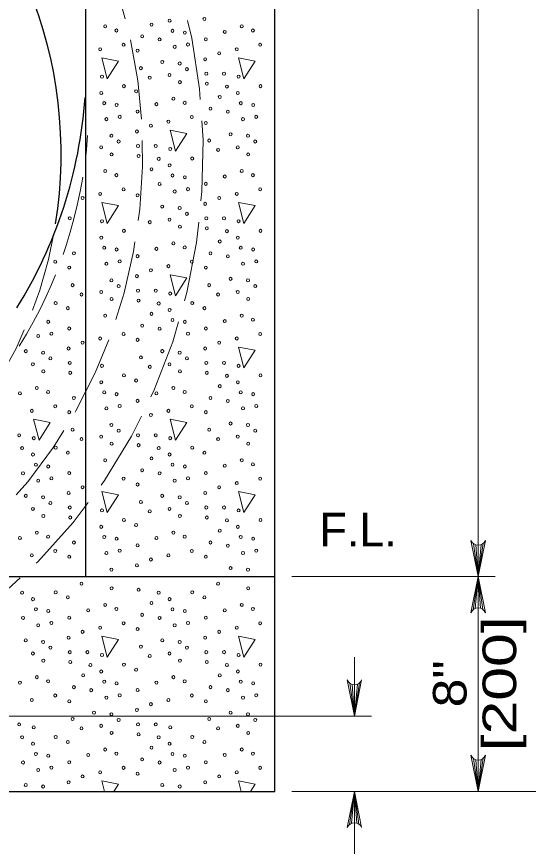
# Model space of a CAD drawing. Extents: x 1083.1 to 1117.1, y 697.4 to 719.4.
# Drawn here: x 1090.667 to 1093.045, y 700.066 to 703.92 of the extents above; entities that cross this region are included whole.
import ezdxf
from ezdxf.enums import TextEntityAlignment as Align

# ---------------------------------------------------------------- set-up
doc = ezdxf.new("R2010")
doc.units = 0
doc.header["$LTSCALE"] = 0.062
doc.linetypes.add('LONG_DASHED', pattern=[7.5, 6, -1.5])
doc.layers.add('1', color=7, linetype='Continuous', lineweight=13)

msp = doc.modelspace()

# ---------------------------------------------------------------- linework, layer by layer
at = {"layer": '1'}
for p, q in [((1092.8115, 701.31858), (1092.8115, 707.72683)), ((1092.79017, 701.47092), (1092.8115, 701.31858)), ((1092.80075, 701.46575), (1092.8115, 701.31858)), ((1092.835, 701.47267), (1092.8115, 701.31858)), ((1092.82517, 701.46683), (1092.8115, 701.31858)), ((1092.8115, 701.46417), (1092.8115, 701.31858)), ((1092.89017, 701.31858), (1091.946, 701.31858)), ((1092.78792, 701.1645), (1092.8115, 701.31858)), ((1092.79783, 701.17033), (1092.8115, 701.31858)), ((1092.8115, 701.31858), (1092.8115, 700.32125)), ((1092.8115, 701.173), (1092.8115, 701.31858)), ((1092.82225, 701.17142), (1092.8115, 701.31858)), ((1092.83283, 701.16625), (1092.8115, 701.31858)), ((1092.23658, 700.67117), (1092.23658, 700.94517)), ((1092.21533, 700.8235), (1092.23658, 700.67117)), ((1092.22583, 700.81833), (1092.23658, 700.67117)), ((1092.26017, 700.82525), (1092.23658, 700.67117)), ((1092.25033, 700.81942), (1092.23658, 700.67117)), ((1092.23658, 700.81675), (1092.23658, 700.67117)), ((1092.31558, 700.67117), (1089.08633, 700.67117)), ((1092.79017, 700.4735), (1092.8115, 700.32125)), ((1092.80075, 700.46842), (1092.8115, 700.32125)), ((1092.835, 700.47533), (1092.8115, 700.32125)), ((1092.82517, 700.4695), (1092.8115, 700.32125)), ((1092.8115, 700.46683), (1092.8115, 700.32125)), ((1091.06317, 700.37008), (1091.07608, 700.32133)), ((1091.14108, 700.355), (1091.06317, 700.37008)), ((1091.11967, 700.32133), (1091.14108, 700.355)), ((1091.75408, 700.32133), (1091.7755, 700.355)), ((1093.83458, 700.32125), (1091.946, 700.32125)), ((1092.21308, 700.16717), (1092.23658, 700.32125)), ((1092.22292, 700.173), (1092.23658, 700.32125)), ((1092.23658, 700.17567), (1092.23658, 700.32125)), ((1092.24742, 700.17408), (1092.23658, 700.32125)), ((1092.25792, 700.16892), (1092.23658, 700.32125)), ((1092.23658, 699.00258), (1092.23658, 700.32125))]:
    msp.add_line(p, q, dxfattribs=at)
at = {"layer": '1', "lineweight": 25}
for p, q in [((1090.98767, 704.14825), (1090.98767, 701.31858)), ((1091.86725, 700.32092), (1091.86725, 704.12275)), ((1086.25067, 701.31858), (1091.86725, 701.31858))]:
    msp.add_line(p, q, dxfattribs=at)
msp.add_lwpolyline([(1086.25067, 706.14383), (1086.25067, 700.32125), (1091.86725, 700.32125)], dxfattribs=at)
at = {"layer": '1'}
for points in [[(1091.06317, 703.72833), (1091.08883, 703.631), (1091.14108, 703.71317)], [(1091.69767, 703.72833), (1091.72325, 703.631), (1091.7755, 703.71317)], [(1091.38042, 703.3925), (1091.40608, 703.29525), (1091.45825, 703.37742)], [(1091.06317, 703.05675), (1091.08883, 702.95942), (1091.14108, 703.04158)], [(1091.69767, 703.05675), (1091.72325, 702.95942), (1091.7755, 703.04158)], [(1091.38042, 702.72092), (1091.40608, 702.6235), (1091.45825, 702.70567)], [(1091.69767, 702.385), (1091.72325, 702.28775), (1091.7755, 702.36992)], [(1090.746, 702.04925), (1090.77167, 701.95192), (1090.82383, 702.03408)], [(1091.38042, 702.04925), (1091.40608, 701.95192), (1091.45825, 702.03408)], [(1091.06317, 701.71342), (1091.08883, 701.61608), (1091.14108, 701.69825)], [(1091.69767, 701.71342), (1091.72325, 701.61608), (1091.7755, 701.69825)], [(1091.06317, 701.04175), (1091.08883, 700.94442), (1091.14108, 701.02658)], [(1091.69767, 701.04175), (1091.72325, 700.94442), (1091.7755, 701.02658)]]:
    msp.add_lwpolyline(points, close=True, dxfattribs=at)
for points in [[(1092.84517, 701.48683), (1092.8115, 701.31858), (1092.77783, 701.48683)], [(1092.77783, 701.15033), (1092.8115, 701.31858), (1092.84517, 701.15033)], [(1092.27025, 700.83942), (1092.23658, 700.67117), (1092.203, 700.83942)], [(1092.84517, 700.4895), (1092.8115, 700.32125), (1092.77783, 700.4895)], [(1091.7755, 700.355), (1091.69767, 700.37008), (1091.7105, 700.32133)], [(1092.203, 700.153), (1092.23658, 700.32125), (1092.27025, 700.153)]]:
    msp.add_lwpolyline(points, dxfattribs=at)
for centre, start, end in [((1092.81145, 701.5004), 202.08782, 337.91395), ((1092.81152, 701.13678), 22.08782, 157.91395), ((1092.23658, 700.85299), 202.08782, 337.91395), ((1092.81145, 700.50305), 202.08782, 337.91395), ((1092.23665, 700.13943), 22.08782, 157.91395)]:
    msp.add_arc(centre, 0.03631, start, end, dxfattribs=at)
at = {"layer": '1', "lineweight": 25}
for centre, major_axis, start_param, end_param in [((1089.04277, 703.2802), (0, 1.93921), 4.5449685, 8.0045958), ((1089.0514, 703.70217), (0, 2.05412), 4.1268954, 4.6353196)]:
    msp.add_ellipse(centre, major_axis=major_axis, ratio=0.944544, start_param=start_param, end_param=end_param, dxfattribs=at)
at = {"layer": '1', "linetype": 'LONG_DASHED'}
for centre, major_axis, start_param, end_param in [((1089.06894, 703.28095), (0, -2.60983), 4.0615652, 8.5327307), ((1089.04094, 703.28499), (0, -2.34206), 4.204739, 8.3489001), ((1089.06299, 703.52479), (0, 2.05412), 4.1268954, 4.6353196), ((1089.04277, 703.2802), (0, 1.93921), 3.3237038, 4.5351133)]:
    msp.add_ellipse(centre, major_axis=major_axis, ratio=0.944544, start_param=start_param, end_param=end_param, dxfattribs=at)
at = {"layer": '1'}
for centre in [(1091.29391, 703.88245), (1091.37787, 703.90058), (1091.53974, 703.90875), (1091.07869, 703.874), (1091.13092, 703.85497), (1091.39161, 703.85345), (1091.44897, 703.84523), (1091.63427, 703.84864), (1091.71309, 703.874), (1091.76533, 703.85497), (1091.25083, 703.82776), (1091.33161, 703.81355), (1091.54662, 703.81439), (1091.05554, 703.76787), (1091.16428, 703.78875), (1091.40181, 703.77907), (1091.46351, 703.78998), (1091.68994, 703.76787), (1091.79869, 703.78875), (1091.22942, 703.76155), (1091.60852, 703.74884), (1091.34419, 703.70899), (1091.42502, 703.702), (1091.5435, 703.72164), (1091.24485, 703.67994), (1091.4587, 703.67541), (1091.54863, 703.65453), (1091.63089, 703.65453), (1091.0641, 703.64093), (1091.28598, 703.6364), (1091.3776, 703.64821), (1091.42587, 703.61524), (1091.6985, 703.64093), (1091.16603, 703.59649), (1091.55116, 703.6083), (1091.64458, 703.5947), (1091.80043, 703.59649), (1091.06066, 703.56476), (1091.22254, 703.57293), (1091.39589, 703.53817), (1091.61111, 703.54662), (1091.69507, 703.56476), (1091.07441, 703.51763), (1091.13177, 703.5094), (1091.31707, 703.51282), (1091.44813, 703.51914), (1091.70881, 703.51763), (1091.76617, 703.5094), (1091.22942, 703.47856), (1091.56803, 703.49194), (1091.64881, 703.47772), (1091.08461, 703.44324), (1091.14631, 703.45416), (1091.37274, 703.43205), (1091.48148, 703.45293), (1091.54662, 703.42573), (1091.71902, 703.44324), (1091.78071, 703.45416), (1091.2263, 703.38582), (1091.29132, 703.41302), (1091.10782, 703.36617), (1091.56205, 703.34412), (1091.66139, 703.37317), (1091.74222, 703.36617), (1091.0604, 703.31238), (1091.1415, 703.33959), (1091.23142, 703.31871), (1091.31369, 703.31871), (1091.3813, 703.30511), (1091.6948, 703.31238), (1091.7759, 703.33959), (1091.10867, 703.27942), (1091.23396, 703.27248), (1091.60318, 703.30057), (1091.74307, 703.27942), (1091.32738, 703.25888), (1091.37787, 703.22893), (1091.48323, 703.26067), (1091.07869, 703.20235), (1091.29391, 703.2108), (1091.71309, 703.20235), (1091.13092, 703.18332), (1091.39161, 703.1818), (1091.44897, 703.17358), (1091.63427, 703.17699), (1091.76533, 703.18332), (1091.16428, 703.1171), (1091.33161, 703.1419), (1091.46351, 703.11833), (1091.54662, 703.14274), (1091.79869, 703.1171), (1090.97412, 703.0772), (1091.05554, 703.09623), (1091.22942, 703.0899), (1091.40181, 703.10742), (1091.60852, 703.0772), (1091.68994, 703.09623), (1091.34419, 703.03734), (1091.5435, 703.04999), (1091.42502, 703.03035), (1091.4587, 703.00376), (1090.91422, 702.98288), (1091.0641, 702.96928), (1091.28598, 702.96475), (1091.3776, 702.97656), (1091.54863, 702.98288), (1091.63089, 702.98288), (1091.6985, 702.96928), (1091.16603, 702.92484), (1091.42587, 702.94359), (1091.55116, 702.93665), (1091.64458, 702.92305), (1091.80043, 702.92484), (1091.06066, 702.89311), (1091.69507, 702.89311), (1091.07441, 702.84598), (1091.39589, 702.86652), (1091.44813, 702.84749), (1091.61111, 702.87497), (1091.70881, 702.84598), (1090.93363, 702.82029), (1091.13177, 702.83775), (1091.22942, 702.80691), (1091.31707, 702.84117), (1091.56803, 702.82029), (1091.64881, 702.80607), (1091.76617, 702.83775), (1090.84708, 702.78128), (1091.08461, 702.7716), (1091.14631, 702.78251), (1091.48148, 702.78128), (1091.71902, 702.7716), (1091.78071, 702.78251), (1090.91221, 702.75408), (1091.29132, 702.74137), (1091.37274, 702.7604), (1091.54662, 702.75408), (1091.10782, 702.69452), (1091.2263, 702.71417), (1091.66139, 702.70152), (1091.74222, 702.69452), (1090.92765, 702.67247), (1091.1415, 702.66794), (1091.56205, 702.67247), (1091.7759, 702.66794), (1090.96878, 702.62893), (1091.0604, 702.64074), (1091.23142, 702.64706), (1091.31369, 702.64706), (1091.3813, 702.63346), (1091.60318, 702.62893), (1091.6948, 702.64074), (1090.84883, 702.58902), (1091.10867, 702.60777), (1091.23396, 702.60083), (1091.32738, 702.58723), (1091.48323, 702.58902), (1091.74307, 702.60777), (1090.90534, 702.56545), (1091.29391, 702.53915), (1091.37787, 702.55728), (1091.53974, 702.56545), (1090.81457, 702.50193), (1091.07869, 702.5307), (1091.39161, 702.51016), (1091.44897, 702.50193), (1091.63427, 702.50534), (1091.71309, 702.5307), (1091.76533, 702.51167), (1090.91221, 702.47109), (1091.25083, 702.48447), (1091.33161, 702.47025), (1091.54662, 702.47109), (1090.76741, 702.43577), (1090.82911, 702.44668), (1091.05554, 702.42458), (1091.16428, 702.44545), (1091.22942, 702.41825), (1091.46351, 702.44668), (1091.68994, 702.42458), (1091.79869, 702.44545), (1090.97412, 702.40555), (1091.60852, 702.40555), (1090.70979, 702.3657), (1090.79062, 702.3587), (1090.9091, 702.37834), (1091.42502, 702.3587), (1091.5435, 702.37834), (1090.7432, 702.30491), (1090.8243, 702.33211), (1090.91422, 702.31124), (1091.24485, 702.33665), (1091.3776, 702.30491), (1091.4587, 702.33211), (1091.54863, 702.31124), (1091.63089, 702.31124), (1090.79147, 702.27194), (1090.91676, 702.265), (1091.0641, 702.29763), (1091.28598, 702.2931), (1091.42587, 702.27194), (1091.55116, 702.265), (1091.6985, 702.29763), (1091.16603, 702.25319), (1091.22254, 702.22963), (1091.64458, 702.2514), (1091.80043, 702.25319), (1090.76149, 702.19487), (1091.06066, 702.22146), (1091.39589, 702.19487), (1091.61111, 702.20332), (1091.69507, 702.22146), (1090.68267, 702.16952), (1090.81372, 702.17584), (1090.93363, 702.14864), (1091.07441, 702.17433), (1091.13177, 702.1661), (1091.31707, 702.16952), (1091.44813, 702.17584), (1091.56803, 702.14864), (1091.70881, 702.17433), (1091.76617, 702.1661), (1090.84708, 702.10963), (1091.14631, 702.11086), (1091.22942, 702.13526), (1091.48148, 702.10963), (1091.64881, 702.13442), (1091.78071, 702.11086), (1090.73834, 702.08875), (1090.91221, 702.08243), (1091.08461, 702.09995), (1091.37274, 702.08875), (1091.54662, 702.08243), (1091.71902, 702.09995), (1091.29132, 702.06972), (1090.92765, 702.00082), (1091.10782, 702.02287), (1091.1415, 701.99629), (1091.56205, 702.00082), (1091.66139, 702.02987), (1091.74222, 702.02287), (1091.7759, 701.99629), (1090.67928, 701.97541), (1090.7469, 701.96181), (1090.96878, 701.95728), (1091.0604, 701.96909), (1091.23142, 701.97541), (1091.31369, 701.97541), (1091.3813, 701.96181), (1091.60318, 701.95728), (1091.6948, 701.96909), (1090.84883, 701.91737), (1091.10867, 701.93612), (1091.23396, 701.92918), (1091.48323, 701.91737), (1091.74307, 701.93612), (1090.69298, 701.91558), (1090.74346, 701.88563), (1090.90534, 701.89381), (1091.32738, 701.91558), (1091.37787, 701.88563), (1091.53974, 701.89381), (1091.07869, 701.85905), (1091.29391, 701.8675), (1091.71309, 701.85905), (1091.76533, 701.84002), (1090.75721, 701.83851), (1090.81457, 701.83028), (1091.25083, 701.81282), (1091.39161, 701.83851), (1091.44897, 701.83028), (1091.63427, 701.83369), (1090.69721, 701.7986), (1090.76741, 701.76412), (1090.82911, 701.77504), (1090.91221, 701.79944), (1091.16428, 701.7738), (1091.33161, 701.7986), (1091.40181, 701.76412), (1091.46351, 701.77504), (1091.54662, 701.79944), (1091.79869, 701.7738), (1090.97412, 701.7339), (1091.22942, 701.7466), (1091.60852, 701.7339), (1091.68994, 701.75293), (1090.70979, 701.69405), (1090.79062, 701.68705), (1090.9091, 701.7067), (1091.34419, 701.69405), (1091.42502, 701.68705), (1091.5435, 701.7067), (1090.8243, 701.66046), (1091.24485, 701.665), (1091.4587, 701.66046), (1090.7432, 701.63326), (1090.91422, 701.63959), (1091.0641, 701.62599), (1091.28598, 701.62145), (1091.3776, 701.63326), (1091.54863, 701.63959), (1091.63089, 701.63959), (1091.6985, 701.62599), (1090.79147, 701.60029), (1090.91676, 701.59335), (1091.16603, 701.58154), (1091.42587, 701.60029), (1091.55116, 701.59335), (1091.64458, 701.57975), (1091.80043, 701.58154), (1091.06066, 701.54981), (1091.22254, 701.55798), (1091.61111, 701.53167), (1091.69507, 701.54981), (1090.68267, 701.49787), (1090.76149, 701.52322), (1090.81372, 701.50419), (1091.07441, 701.50268), (1091.13177, 701.49445), (1091.31707, 701.49787), (1091.39589, 701.52322), (1091.44813, 701.50419), (1091.70881, 701.50268), (1091.76617, 701.49445), (1090.93363, 701.47699), (1091.22942, 701.46361), (1091.56803, 701.47699), (1091.64881, 701.46277), (1090.73834, 701.4171), (1090.84708, 701.43798), (1091.08461, 701.4283), (1091.14631, 701.43921), (1091.37274, 701.4171), (1091.48148, 701.43798), (1091.71902, 701.4283), (1091.78071, 701.43921), (1090.91221, 701.41078), (1091.29132, 701.39807), (1091.54662, 701.41078), (1091.10782, 701.35123), (1091.2263, 701.37087), (1091.66139, 701.35822), (1091.74222, 701.35123), (1090.96878, 701.28563), (1091.10867, 701.26447), (1091.60318, 701.28563), (1091.74307, 701.26447), (1090.69298, 701.24393), (1090.84883, 701.24572), (1091.23396, 701.25753), (1091.32738, 701.24393), (1091.48323, 701.24572), (1090.74346, 701.21398), (1090.90534, 701.22216), (1091.07869, 701.1874), (1091.29391, 701.19585), (1091.37787, 701.21398), (1091.53974, 701.22216), (1091.71309, 701.1874), (1090.75721, 701.16686), (1090.81457, 701.15863), (1090.99987, 701.16204), (1091.13092, 701.16837), (1091.39161, 701.16686), (1091.44897, 701.15863), (1091.63427, 701.16204), (1091.76533, 701.16837), (1090.69721, 701.12695), (1090.91221, 701.12779), (1091.25083, 701.14117), (1091.33161, 701.12695), (1091.54662, 701.12779), (1090.76741, 701.09247), (1090.82911, 701.10339), (1091.05554, 701.08128), (1091.16428, 701.10216), (1091.22942, 701.07495), (1091.40181, 701.09247), (1091.46351, 701.10339), (1091.68994, 701.08128), (1091.79869, 701.10216), (1090.9091, 701.03505), (1090.97412, 701.06225), (1091.5435, 701.03505), (1091.60852, 701.06225), (1090.70979, 701.0224), (1090.79062, 701.0154), (1091.24485, 700.99335), (1091.34419, 701.0224), (1091.42502, 701.0154), (1090.7432, 700.96161), (1090.8243, 700.98881), (1090.91422, 700.96794), (1090.99648, 700.96794), (1091.0641, 700.95434), (1091.3776, 700.96161), (1091.4587, 700.98881), (1091.54863, 700.96794), (1091.63089, 700.96794), (1091.6985, 700.95434), (1090.79147, 700.92865), (1090.91676, 700.92171), (1091.28598, 700.9498), (1091.42587, 700.92865), (1091.55116, 700.92171), (1091.01018, 700.9081), (1091.06066, 700.87816), (1091.16603, 700.9099), (1091.22254, 700.88633), (1091.64458, 700.9081), (1091.69507, 700.87816), (1091.80043, 700.9099), (1090.76149, 700.85157), (1090.97671, 700.86003), (1091.39589, 700.85157), (1091.61111, 700.86003), (1090.68267, 700.82622), (1090.81372, 700.83254), (1090.93363, 700.80534), (1091.07441, 700.83103), (1091.13177, 700.82281), (1091.31707, 700.82622), (1091.44813, 700.83254), (1091.56803, 700.80534), (1091.70881, 700.83103), (1091.76617, 700.82281), (1090.84708, 700.76633), (1091.01441, 700.79113), (1091.14631, 700.76756), (1091.22942, 700.79197), (1091.48148, 700.76633), (1091.64881, 700.79113), (1091.78071, 700.76756), (1090.73834, 700.74545), (1090.91221, 700.73913), (1091.08461, 700.75665), (1091.29132, 700.72642), (1091.37274, 700.74545), (1091.54662, 700.73913), (1091.71902, 700.75665), (1091.02699, 700.68657), (1091.2263, 700.69922), (1091.66139, 700.68657), (1090.92765, 700.65752), (1091.10782, 700.67958), (1091.1415, 700.65299), (1091.56205, 700.65752), (1091.74222, 700.67958), (1091.7759, 700.65299), (1090.67928, 700.63211), (1090.7469, 700.61851), (1090.96878, 700.61398), (1091.0604, 700.62579), (1091.23142, 700.63211), (1091.31369, 700.63211), (1091.3813, 700.61851), (1091.60318, 700.61398), (1091.6948, 700.62579), (1090.69298, 700.57228), (1090.84883, 700.57407), (1091.10867, 700.59282), (1091.23396, 700.58588), (1091.32738, 700.57228), (1091.48323, 700.57407), (1091.74307, 700.59282), (1090.74346, 700.54234), (1090.90534, 700.55051), (1091.37787, 700.54234), (1091.53974, 700.55051), (1090.75721, 700.49521), (1091.07869, 700.51575), (1091.13092, 700.49672), (1091.29391, 700.5242), (1091.39161, 700.49521), (1091.71309, 700.51575), (1091.76533, 700.49672), (1090.69721, 700.4553), (1090.81457, 700.48698), (1090.91221, 700.45614), (1090.99987, 700.49039), (1091.25083, 700.46952), (1091.33161, 700.4553), (1091.44897, 700.48698), (1091.54662, 700.45614), (1091.63427, 700.49039), (1090.76741, 700.42082), (1090.82911, 700.43174), (1091.16428, 700.43051), (1091.40181, 700.42082), (1091.46351, 700.43174), (1091.79869, 700.43051), (1090.97412, 700.3906), (1091.05554, 700.40963), (1091.22942, 700.4033), (1091.60852, 700.3906), (1091.68994, 700.40963), (1090.70979, 700.35075), (1090.79062, 700.34375), (1090.9091, 700.3634), (1091.34419, 700.35075), (1091.42502, 700.34375), (1091.5435, 700.3634)]:
    msp.add_ellipse(centre, major_axis=(0, 0.00718), ratio=0.944544, dxfattribs=at)
at = {"layer": '1', "linetype": 'LONG_DASHED'}
msp.add_ellipse((1091.34419, 702.3657), major_axis=(0, 0.00718), ratio=0.944544, dxfattribs=at)

# ---------------------------------------------------------------- texts
at = {"layer": '1'}
msp.add_text('F.L.', height=0.156, dxfattribs=at).set_placement((1092.07408, 701.459))
for s, width, p in [('[200]', 1.35, (1092.98817, 700.82075)), ('8"', 1.15, (1092.75742, 700.82075))]:
    msp.add_text(s, height=0.156, rotation=90, dxfattribs=dict(at, width=width)).set_placement(p, align=Align.CENTER)

doc.saveas('drawing.dxf')
